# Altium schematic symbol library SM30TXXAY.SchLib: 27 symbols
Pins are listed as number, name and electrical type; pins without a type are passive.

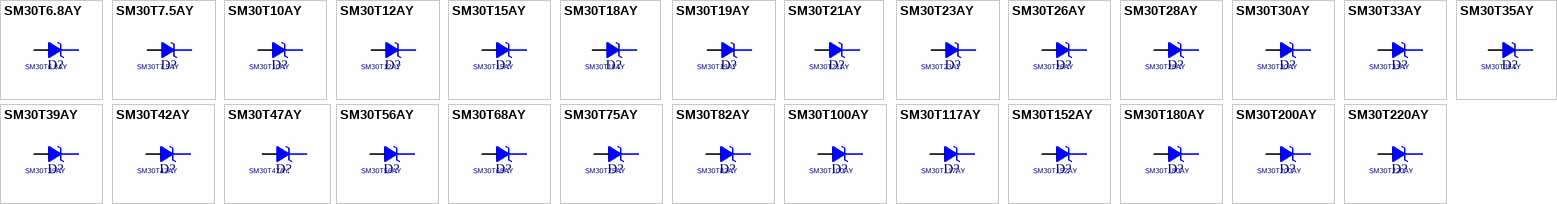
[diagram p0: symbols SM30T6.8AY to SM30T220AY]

## SM30T6.8AY
designator D?
footprint ST_SMC
pins: 1 K, 2 A

## SM30T7.5AY
designator D?
footprint ST_SMC
pins: 1 K, 2 A

## SM30T10AY
designator D?
footprint ST_SMC
pins: 1 K, 2 A

## SM30T12AY
designator D?
footprint ST_SMC
pins: 1 K, 2 A

## SM30T15AY
designator D?
footprint ST_SMC
pins: 1 K, 2 A

## SM30T18AY
designator D?
footprint ST_SMC
pins: 1 K, 2 A

## SM30T19AY
designator D?
footprint ST_SMC
pins: 1 K, 2 A

## SM30T21AY
designator D?
footprint ST_SMC
pins: 1 K, 2 A

## SM30T23AY
designator D?
footprint ST_SMC
pins: 1 K, 2 A

## SM30T26AY
designator D?
footprint ST_SMC
pins: 1 K, 2 A

## SM30T28AY
designator D?
footprint ST_SMC
pins: 1 K, 2 A

## SM30T30AY
designator D?
footprint ST_SMC
pins: 1 K, 2 A

## SM30T33AY
designator D?
footprint ST_SMC
pins: 1 K, 2 A

## SM30T35AY
designator D?
footprint ST_SMC
pins: 1 K, 2 A

## SM30T39AY
designator D?
footprint ST_SMC
pins: 1 K, 2 A

## SM30T42AY
designator D?
footprint ST_SMC
pins: 1 K, 2 A

## SM30T47AY
designator D?
footprint ST_SMC
pins: 1 K, 2 A

## SM30T56AY
designator D?
footprint ST_SMC
pins: 1 K, 2 A

## SM30T68AY
designator D?
footprint ST_SMC
pins: 1 K, 2 A

## SM30T75AY
designator D?
footprint ST_SMC
pins: 1 K, 2 A

## SM30T82AY
designator D?
footprint ST_SMC
pins: 1 K, 2 A

## SM30T100AY
designator D?
footprint ST_SMC
pins: 1 K, 2 A

## SM30T117AY
designator D?
footprint ST_SMC
pins: 1 K, 2 A

## SM30T152AY
designator D?
footprint ST_SMC
pins: 1 K, 2 A

## SM30T180AY
designator D?
footprint ST_SMC
pins: 1 K, 2 A

## SM30T200AY
designator D?
footprint ST_SMC
pins: 1 K, 2 A

## SM30T220AY
designator D?
footprint ST_SMC
pins: 1 K, 2 A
